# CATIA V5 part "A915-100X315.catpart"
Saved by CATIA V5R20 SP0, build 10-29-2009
Part number: A915-100X315
Source: Unknown
Property "A": "0.000"
Property "ARTICLENO": "A915-100X315"
Property "BOMINFO": "A915-100X315"
Property "CODE": "A915-100X315"
Property "CREATOR": "CADENAS GmbH"
Property "D": "13.500"
Property "D1": "20.000"
Property "FORM": "B"
Property "L": "315.000"
Property "L1": "40.000"
Property "L2": "235.000"
Property "LINA": "A915-100X315"
Property "NB": "A915-100X315"
Property "NBSYN": "$CODE."
Property "NN": "A915"
Property "NT": "VDI 3357 Wear Plates, steel"
Property "SCREW": "M12x25"
Property "SUPPLIER": "CF"
Property "T": "13.000"
Property "W": "100.000"
Bounding box of the stored display mesh (mm): x 0 to 20, y 0 to 315, z -50 to 50
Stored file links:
  C:\Users\borellobunino\Desktop\3D X SITO CF\A915\GSB_OILLESS_G22501100315\CATIAV5\A915-100X315.catpart
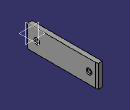
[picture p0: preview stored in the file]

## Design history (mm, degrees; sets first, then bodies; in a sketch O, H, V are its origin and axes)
Body1 "Geometry.1" (main body)
  Solid1 "A915-100X315.catpart": solid without history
